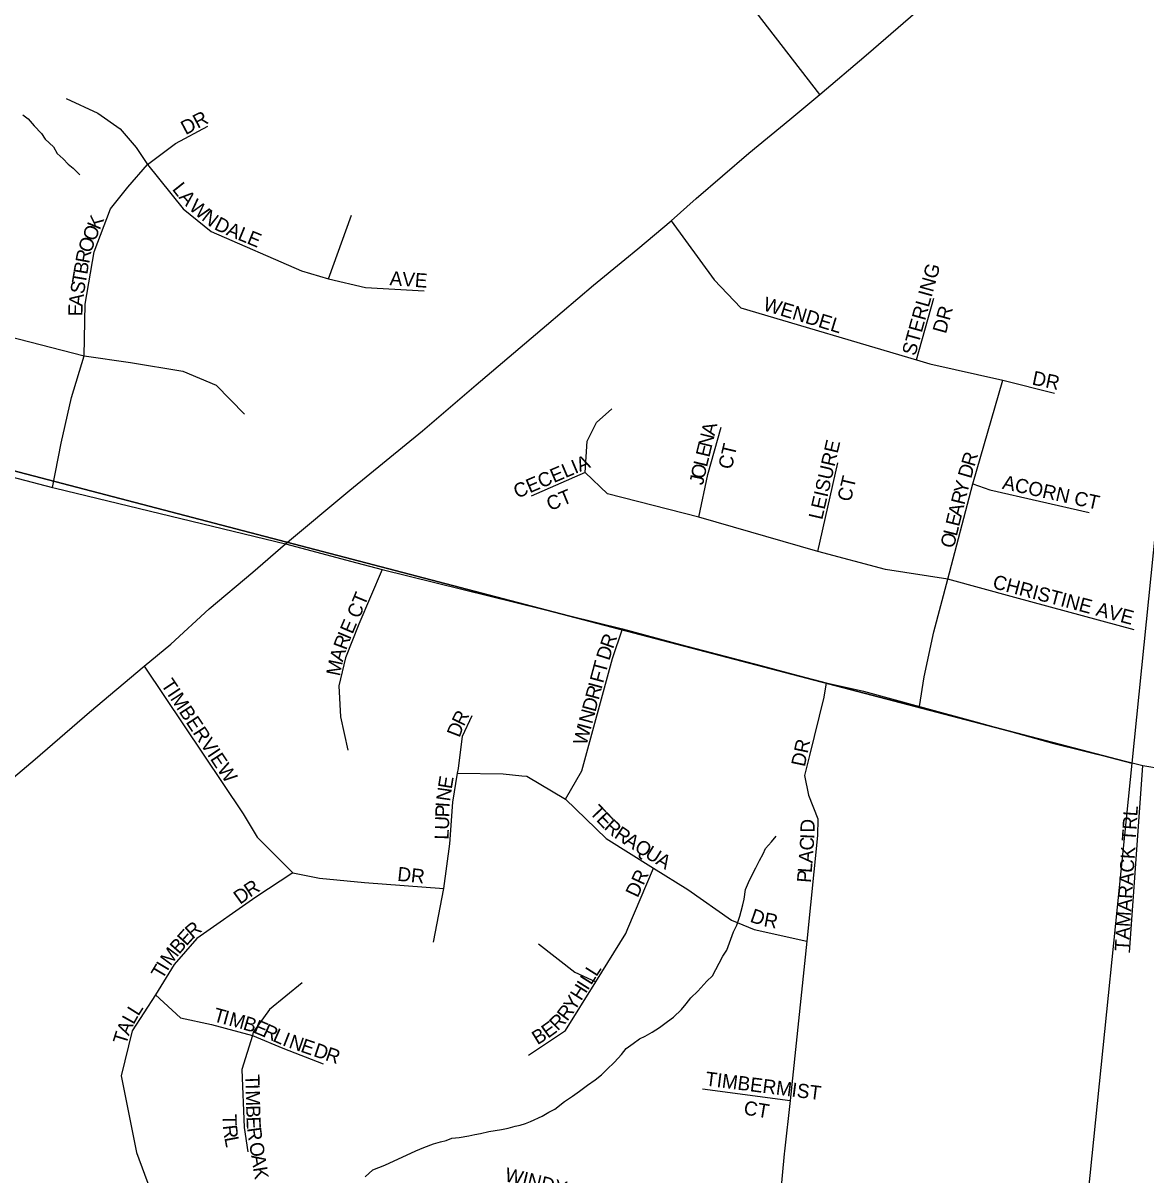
# Model space of a CAD drawing. Extents: x 1310247 to 1552180, y 377264 to 706493.
# Drawn here: x 1435699 to 1439680, y 480751 to 484836 of the extents above; entities that cross this region are included whole.
import ezdxf

# ---------------------------------------------------------------- set-up
doc = ezdxf.new("R2010")
doc.units = 0
for name, color, linetype in [('GM_X_Minor_River', 7, 'Continuous'), ('GM_X_Section', 7, 'Continuous'), ('GM_X_Township_Road', 7, 'Continuous'), ('GM_X_Township_Subdivision', 7, 'Continuous'), ('GM_X_Township_Subdivision_Text', 7, 'Continuous'), ('GM_X_US_Route', 7, 'Continuous')]:
    doc.layers.add(name, color=color, linetype=linetype)

msp = doc.modelspace()

# ---------------------------------------------------------------- linework, layer by layer
at = {"layer": 'GM_X_Minor_River'}
for points in [[(1435697.9, 484511), (1435717.6, 484496.4), (1435738.9, 484471.6), (1435764.2, 484444.8), (1435777.7, 484424.3), (1435807, 484397.3), (1435820.3, 484372.8), (1435841.9, 484354.1), (1435859.4, 484335.5), (1435877, 484320.9), (1435900.5, 484298.1)], [(1436912.7, 480744.4), (1436939.5, 480769.6), (1436982.1, 480786.4), (1437092, 480837.2), (1437120.4, 480848.4), (1437154.9, 480861.4), (1437179.2, 480868.7), (1437199.4, 480874.1), (1437219.7, 480881.5), (1437245.9, 480884.7), (1437280.2, 480889.7), (1437300.4, 480895.1), (1437320.6, 480898.5), (1437350.9, 480905.6), (1437395.2, 480912.3), (1437419.4, 480917.5), (1437443.7, 480924.8), (1437461.9, 480928.3), (1437480.1, 480933.8), (1437498.4, 480941.2), (1437539.1, 480960.1), (1437563.6, 480973.4), (1437584, 480984.8), (1437618.9, 481011.8), (1437647.5, 481031), (1437672.1, 481048.3), (1437700.8, 481069.5), (1437727.5, 481088.8), (1437750.1, 481106.2), (1437768.7, 481125.7), (1437795.5, 481151), (1437820.4, 481178.3), (1437837.1, 481199.9), (1437861.7, 481217.2), (1437884.3, 481234.6), (1437904.6, 481244), (1437929.1, 481257.3), (1437955.7, 481274.5), (1437984.4, 481295.7), (1438004.9, 481311.2), (1438033.8, 481338.4), (1438050.4, 481358), (1438067.1, 481379.5), (1438091.9, 481402.8), (1438123, 481438), (1438143.6, 481457.5), (1438167, 481502.9), (1438179.8, 481526.6), (1438194.4, 481548.2), (1438218.4, 481613.8), (1438229.2, 481637.5), (1438240.1, 481669.3), (1438244.6, 481687.2), (1438251.3, 481709.1), (1438255.9, 481729), (1438260.9, 481763), (1438271.7, 481788.8), (1438286.7, 481820.4), (1438297.3, 481840.2), (1438310.1, 481865.9), (1438322.8, 481889.6), (1438331.4, 481909.4), (1438352.2, 481932.8), (1438368.8, 481952.4)]]:
    msp.add_lwpolyline(points, dxfattribs=at)
at = {"layer": 'GM_X_Section'}
for points in [[(1434523.9, 489065.4), (1440171.6, 487550.2), (1439630.2, 482211.5), (1433994.3, 483685)], [(1433994.3, 483685), (1439630.2, 482211.5), (1439094.6, 476954.7), (1433497.3, 478156.7)]]:
    msp.add_lwpolyline(points, close=True, dxfattribs=at)
at = {"layer": 'GM_X_Township_Road'}
for points in [[(1429426.1, 484991.4), (1430223.6, 484989.7), (1431035.7, 484988), (1431086.6, 484986.1), (1431113.4, 484977.8), (1431129.2, 484959.3), (1431134.7, 484943.6), (1431128.2, 484845.5), (1431093.5, 484521.3), (1431050.5, 484110.7), (1431036.6, 483786.8), (1431930.4, 483759), (1432525.7, 483732.4), (1433313.7, 483704.9), (1433388, 483700.2), (1433815.7, 483679.2), (1434006.9, 483666.3), (1434168.3, 483614.6), (1434238.2, 483598.8), (1435803.9, 483188.9), (1435814.4, 483186.1), (1436629.6, 482989.6)], [(1436629.6, 482989.6), (1436883.1, 482922.1)], [(1436883.1, 482922.1), (1436972.2, 482898.3), (1437824, 482687.6), (1438030, 482631.8), (1438315.4, 482557.9), (1438429.3, 482527.2), (1438546.8, 482496.4), (1438679, 482467.1), (1438877, 482412.7), (1439076.9, 482358.3), (1439353.4, 482281), (1439669.4, 482202.8), (1439877.8, 482167.5), (1440100.5, 482127.2), (1440471.6, 482063.9), (1440597.5, 482044.6), (1441063.4, 481955.8), (1441309.6, 481918.7), (1441615.2, 481868.3), (1442055, 481796.8)]]:
    msp.add_lwpolyline(points, dxfattribs=at)
at = {"layer": 'GM_X_Township_Subdivision'}
for points in [[(1438523.8, 484583), (1438298.6, 484875), (1438213.5, 484984), (1438090.2, 485092.9), (1437891.5, 485280.2), (1437733.8, 485343.5), (1437389.1, 485386.2), (1437137.1, 485414.3), (1437083.4, 485421.6)], [(1435851.7, 484568.5), (1435964.5, 484516.9), (1436043.5, 484460.5), (1436099.9, 484394.9), (1436140.2, 484334.8), (1436267.2, 484177.2), (1436366.7, 484097.3), (1436686.7, 483957.2), (1436781.8, 483928.6), (1436913.7, 483898), (1437121.6, 483886.7)], [(1431093.5, 484521.3), (1431274.2, 484507.9), (1431389.2, 484489.5), (1431489.4, 484459.2), (1431667.7, 484325), (1431738.5, 484272.6), (1431824.9, 484238.6), (1431912.2, 484227.5), (1432064.9, 484228.4), (1432541.9, 484192.4), (1432959.8, 484176.2), (1433348.7, 484161.1), (1433385.7, 484159.7), (1434010.4, 484124.9), (1434267.8, 484057.9), (1434342.3, 484038.5), (1435645.4, 483725.6), (1435915.9, 483656.3), (1436080.5, 483632.1), (1436265.9, 483601.5), (1436383.5, 483551.5), (1436483.9, 483448.7)], [(1435803.9, 483188.9), (1435833.9, 483346.8), (1435871, 483508), (1435915.9, 483656.3), (1435920, 483838.6), (1435950.8, 484024.1), (1436009.6, 484176.8), (1436070.8, 484254.2), (1436140.2, 484334.8), (1436240.1, 484408.9), (1436354.5, 484470.1)], [(1436781.8, 483928.6), (1436863.5, 484154.6)], [(1437996.8, 484134.9), (1438149.9, 483925), (1438244.1, 483826.5), (1438866.6, 483641.3), (1438913.6, 483627.3), (1439173.2, 483569.2), (1439355.4, 483524.1)], [(1438866.6, 483641.3), (1438928.3, 483860.9)], [(1438877, 482412.7), (1438893.7, 482518), (1438928.2, 482676.8), (1438977.8, 482864.2), (1439066.9, 483201.8), (1439173.2, 483569.2)], [(1439639, 482684.5), (1439215.1, 482798.9), (1438977.8, 482864.2), (1438757.4, 482898.8), (1438517, 482961.5), (1438094.7, 483084), (1437771.1, 483166.3), (1437692.1, 483242.1), (1437698.6, 483353.3), (1437732.5, 483419.4), (1437787.2, 483467.7)], [(1438094.7, 483084), (1438127.3, 483235.6), (1438174, 483403.2)], [(1438517, 482961.5), (1438588.2, 483275.9)], [(1437692.1, 483242.1), (1437500.4, 483158.3)], [(1439066.9, 483201.8), (1439126.5, 483180.9), (1439479.4, 483100.2)], [(1436972.2, 482898.3), (1436890, 482704.1), (1436842.1, 482585.4), (1436819.3, 482486.3), (1436824.8, 482375.5), (1436850.7, 482257.6)], [(1437622.9, 482084.1), (1437680.1, 482184.5), (1437788.6, 482582.3), (1437824, 482687.6)], [(1436128.1, 482555.5), (1436479.7, 482032.1), (1436529.7, 481948.8), (1436655.5, 481822.1), (1436749.8, 481803.6), (1436909.8, 481787.8), (1437191, 481766.6)], [(1438546.8, 482496.4), (1438538.6, 482445.5), (1438487.5, 482238.7), (1438470.2, 482167.9), (1438484, 482097.8), (1438516.6, 482013.9), (1438515.5, 481955.3), (1438478.5, 481580.6), (1438419.3, 481015.3), (1438398.9, 480835.8), (1438398, 480826)], [(1437154.9, 481576.9), (1437191, 481766.6), (1437212.3, 481925.7), (1437223.3, 482073.7), (1437239.9, 482175.5), (1437242.8, 482193), (1437257.6, 482307.8), (1437291.8, 482380.9)], [(1439622.4, 481540.6), (1439669.4, 482202.8)], [(1437239.9, 482175.5), (1437240, 482175.5), (1437400.9, 482173.6), (1437467.8, 482167)], [(1437467.8, 482167), (1437485.1, 482165.3), (1437622.9, 482084.1), (1437766.6, 481944), (1437934, 481839.7), (1438055.8, 481763.8), (1438210.3, 481654.6), (1438291.6, 481621.3), (1438478.5, 481580.6)], [(1437843.9, 481625), (1437934, 481839.7)], [(1436655.5, 481822.1), (1436524.1, 481736), (1436315.1, 481589.9), (1436235.5, 481497.3), (1436168.9, 481390), (1436085.7, 481262.4), (1436046.8, 481103.2), (1436101.6, 480830.9), (1436198.5, 480568.5)], [(1437490.7, 481176.3), (1437622, 481263.3), (1437729.5, 481435.7), (1437836.6, 481607.4), (1437843.9, 481625)], [(1437526.2, 481571.3), (1437654.9, 481470.2), (1437729.5, 481435.7)], [(1436688.8, 481432.6), (1436572.7, 481338.1), (1436515.6, 481257.9), (1436512.1, 481246.4), (1436474.8, 481124.9), (1436483.4, 480919.9), (1436496.4, 480833.1)], [(1436168.9, 481390), (1436257.7, 481308.6), (1436366.9, 481284.6), (1436512.1, 481246.4), (1436620.3, 481201.3), (1436762.7, 481145.8)], [(1438107.8, 481056.3), (1438419.3, 481015.3)], [(1438398, 480826), (1438364.8, 480468.4)]]:
    msp.add_lwpolyline(points, dxfattribs=at)
at = {"layer": 'GM_X_US_Route'}
for points in [[(1437832.6, 483997), (1437879.1, 484035), (1437996.8, 484134.9), (1438085.4, 484213.9), (1438272.4, 484375), (1438418, 484494.3), (1438523.8, 484583), (1438688.1, 484721.6), (1438889.6, 484895.6), (1439083, 485056.8), (1439224.1, 485179.2), (1439290.6, 485232.6), (1439400.5, 485323.7), (1439429.7, 485348.2)], [(1435580.1, 482089.8), (1435742.1, 482225.2), (1435934.7, 482391.9), (1436128.1, 482555.5), (1436223.1, 482633.7), (1436359.3, 482758.6), (1436514.1, 482888.3), (1436629.6, 482989.6), (1436857.3, 483179.2), (1437115.2, 483390.3), (1437305.4, 483553.1), (1437555.2, 483764.3), (1437721.2, 483906.1), (1437832.6, 483997)]]:
    msp.add_lwpolyline(points, dxfattribs=at)

# ---------------------------------------------------------------- texts
at = {"layer": 'GM_X_Township_Subdivision_Text'}
for s, rotation, p in [('DR', 27.894, (1436275.5, 484438)), ('L', 308.4273, (1436225.7, 484246.3)), ('A', 310.9226, (1436249.1, 484216.9)), ('W', 319.9556, (1436284.1, 484177.6)), ('K', 67.5289, (1435970.7, 484099.8)), ('N', 321.6603, (1436329.1, 484139.8)), ('O', 67.6466, (1435954, 484059.1)), ('D', 334.1074, (1436373.7, 484106.2)), ('A', 337.7403, (1436416.4, 484085.6)), ('O', 71.2298, (1435940.1, 484018.2)), ('L', 337.6912, (1436457.1, 484068.9)), ('E', 337.6912, (1436489.7, 484055.5)), ('R', 79.3878, (1435933.3, 483981.1)), ('T', 80.4209, (1435920.9, 483907.6)), ('B', 80.4119, (1435926.7, 483942.3)), ('AVE', 355.9127, (1436997.8, 483906.7)), ('STERLING', 74.5213, (1438862.4, 483653.5)), ('S', 80.6005, (1435915.1, 483872.9)), ('A', 83.4836, (1435910.2, 483829.8)), ('E', 89.0028, (1435909.7, 483795.9)), ('WENDEL', 343.113, (1438319.8, 483818.3)), ('DR', 74.4781, (1438970.8, 483731.9)), ('DR', 348.1073, (1439273.8, 483554.5)), ('N', 76.2871, (1438140.2, 483327.6)), ('A', 76.2952, (1438150.7, 483370.3)), ('E', 76.2917, (1438131.9, 483293.4)), ('CT', 76.7605, (1438211.3, 483250.6)), ('LEISURE', 76.932, (1438532.3, 483072.3)), ('CECELIA', 23.0707, (1437451, 483149.2)), ('R', 73.7427, (1439072.4, 483260.6)), ('O', 77.5648, (1438114.2, 483216.5)), ('L', 76.3613, (1438123.6, 483259.2)), ('D', 73.8775, (1439060.1, 483218.3)), ('J', 78.5829, (1438109.9, 483195.2)), ('CT', 76.7605, (1438633.7, 483136.2)), ('Y', 75.7915, (1439046, 483163.4)), ('ACORN CT', 347.5611, (1439168.3, 483184.9)), ('CT', 22.3798, (1437567.5, 483104.9)), ('R', 76.2103, (1439036.5, 483125)), ('E', 76.2056, (1439017.6, 483048.1)), ('A', 76.197, (1439026, 483082.3)), ('O', 76.2076, (1438998.8, 482971.2)), ('L', 76.2056, (1439009.3, 483013.9)), ('CHRISTINE AVE', 345.1742, (1439133.5, 482832.8)), ('CT', 67.6202, (1436891.6, 482721.7)), ('E', 67.0642, (1436867, 482666.7)), ('R', 69.3096, (1436844.6, 482609.8)), ('I', 67.0642, (1436858.4, 482646.4)), ('R', 70.632, (1437790.7, 482614.4)), ('A', 73.8004, (1436832.6, 482568.6)), ('D', 72.0247, (1437777.2, 482572.8)), ('M', 78.2913, (1436822.2, 482517.9)), ('T', 74.9929, (1437764.7, 482526.8)), ('F', 75.0064, (1437755.6, 482492.8)), ('TIMBERVIEW', 303.5111, (1436186.5, 482490.1)), ('R', 75.0037, (1437739.7, 482433.3)), ('I', 74.9883, (1437749.9, 482471.5)), ('D', 74.9989, (1437728.3, 482390.8)), ('N', 74.9989, (1437716.9, 482348.3)), ('R', 63.7065, (1437261.8, 482339.7)), ('D', 68.8683, (1437246.4, 482299.8)), ('W', 75.0014, (1437696.4, 482271.8)), ('I', 75.0089, (1437711.2, 482327)), ('DR', 78.1073, (1438470.7, 482196.5)), ('E', 80.5736, (1437219, 482117.8)), ('N', 81.9858, (1437212.9, 482074.5)), ('P', 88.0735, (1437210.4, 482018.8)), ('I', 86.1496, (1437211.5, 482053.5)), ('T', 313.6476, (1437704.6, 482034.5)), ('E', 313.6697, (1437728.9, 482009)), ('TAMARACK TRL', 86.3255, (1439618.9, 481543.9)), ('U', 88.0738, (1437208.9, 481974.8)), ('R', 318.1957, (1437756.3, 481980.5)), ('D', 89.5141, (1438505.3, 481965.3)), ('L', 88.0735, (1437207.7, 481939.6)), ('R', 326.109, (1437791.8, 481949.5)), ('A', 327.6796, (1437825.9, 481926.6)), ('I', 87.5807, (1438504.3, 481941.5)), ('Q', 327.7549, (1437863.2, 481903.1)), ('U', 328.0252, (1437900.6, 481879.5)), ('C', 85.6519, (1438501.2, 481900.1)), ('A', 329.1744, (1437938.9, 481855.6)), ('A', 85.6357, (1438497.9, 481856.3)), ('DR', 353.9946, (1437024.5, 481794.7)), ('DR', 64.8007, (1437878, 481731.9)), ('P', 85.638, (1438492.5, 481786.1)), ('L', 85.6392, (1438495.2, 481821.2)), ('R', 33.424, (1436503.6, 481734.1)), ('D', 35.6393, (1436468.3, 481708.8)), ('D', 340.8946, (1438273.4, 481650)), ('R', 349.338, (1438322.6, 481633.6)), ('E', 48.0828, (1436278.3, 481561.1)), ('R', 40.9872, (1436300.6, 481586.2)), ('B', 48.6176, (1436252.2, 481531.5)), ('M', 53.5581, (1436221.6, 481489.9)), ('I', 59.1692, (1436211, 481472.1)), ('T', 59.1674, (1436193, 481441.9)), ('L', 57.6801, (1437731.8, 481451.9)), ('H', 57.6801, (1437677.7, 481366.3)), ('I', 57.6801, (1437701.2, 481403.5)), ('L', 57.6801, (1437713, 481422.1)), ('Y', 57.6801, (1437654.2, 481329.2)), ('L', 57.7276, (1436107.8, 481312.3)), ('T', 344.655, (1436370.3, 481297)), ('R', 53.3345, (1437628.2, 481294)), ('L', 60.7666, (1436091, 481282.1)), ('I', 344.6748, (1436404.3, 481287.7)), ('M', 344.6626, (1436425.5, 481281.9)), ('B', 343.4392, (1436476.1, 481268)), ('E', 337.6659, (1436512.8, 481257.2)), ('E', 35.9522, (1437560, 481234.1)), ('R', 44.6434, (1437594.7, 481260.1)), ('T', 72.9226, (1436064.5, 481210.6)), ('A', 66.8446, (1436074.3, 481242.9)), ('R', 335.6023, (1436545, 481244)), ('L', 335.9759, (1436581.3, 481227.5)), ('I', 338.5734, (1436615.7, 481212.2)), ('B', 31.6066, (1437522.9, 481211.1)), ('N', 340.9586, (1436638.3, 481203.4)), ('E', 341.193, (1436680.1, 481189)), ('D', 341.2056, (1436725.9, 481173.4)), ('R', 341.1964, (1436767.6, 481159.2)), ('T', 271.3935, (1436487.3, 481107.9)), ('TIMBERMIST', 352.7111, (1438115.9, 481068.7)), ('I', 271.3769, (1436488.2, 481072.8)), ('M', 271.3963, (1436488.7, 481050.8)), ('CT', 350.5377, (1438251.7, 480966.2)), ('B', 271.3966, (1436490, 480998)), ('T', 270.847, (1436406.6, 480966.7)), ('E', 272.566, (1436491, 480957.3)), ('R', 276.6577, (1436407.5, 480926.1)), ('R', 277.7305, (1436493, 480917.2)), ('L', 280.6437, (1436412.7, 480883.1)), ('O', 279.0453, (1436500.6, 480863.7)), ('A', 279.0419, (1436507.5, 480820.2)), ('K', 279.0312, (1436514.4, 480776.8)), ('WINDY', 346.5516, (1437404.1, 480729.7))]:
    msp.add_text(s, height=50, rotation=rotation, dxfattribs=at).set_placement(p)

doc.saveas('drawing.dxf')
